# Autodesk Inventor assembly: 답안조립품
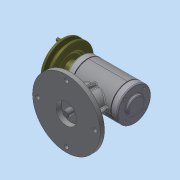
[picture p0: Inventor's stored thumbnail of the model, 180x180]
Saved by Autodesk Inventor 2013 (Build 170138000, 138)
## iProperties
Created: 2018-06
Part Number: 답안조립품
Document SubType Name: Assembly
Designer: dgall
Author: dgall
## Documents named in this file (18)
- C:\Users\dgall\Desktop\380607V1012\답안조립품.iam
- C:\Users\dgall\Desktop\380607V1012\본체.ipt
- C:\Users\dgall\Desktop\380607V1012\V-벨트풀리.ipt
- C:\Users\dgall\Desktop\380607V1012\가변스프링.ipt
- C:\Users\dgall\Desktop\380607V1012\뒤커버.ipt
- C:\Users\dgall\Desktop\380607V1012\멈춤나사 M3x8.ipt
- C:\Users\dgall\Desktop\380607V1012\베어링 6201.ipt
- C:\Users\dgall\Desktop\380607V1012\베어링 6202.ipt
- C:\Users\dgall\Desktop\380607V1012\본체커버.ipt
- C:\Users\dgall\Desktop\380607V1012\슬라이드.ipt
- C:\Users\dgall\Desktop\380607V1012\앞커버.ipt
- C:\Users\dgall\Desktop\380607V1012\오일 실 12 22 7.ipt
- 오일 실 12 22 7.ipt
- C:\Users\dgall\Desktop\380607V1012\키 4x4x18.ipt
- 키 4x4x18.ipt
- C:\Users\dgall\Desktop\380607V1012\편심축.ipt
- C:\Users\dgall\Desktop\380607V1012\개스킷.ipt
- C:\Users\dgall\Desktop\380607V1012\볼트 M3x0.5x8.ipt
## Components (4 placed, 3 different names)
1. V-벨트풀리:1
2. 가변스프링:1
3. 개스킷:1
4. 개스킷:2
